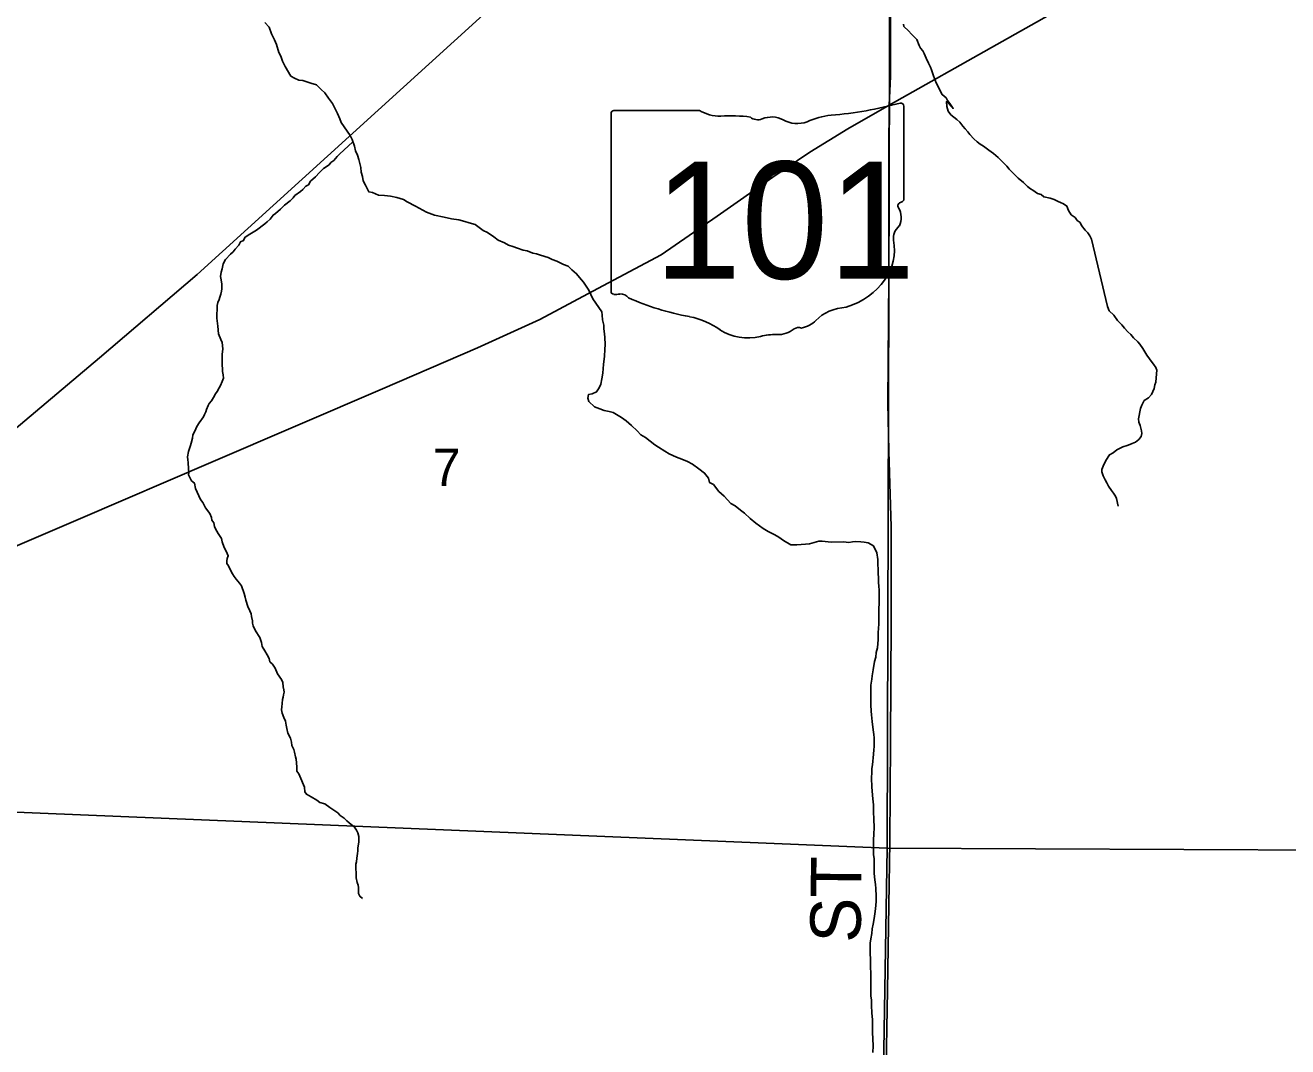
# Model space of a CAD drawing. Extents: x 0 to 34, y 0 to 22.
# Drawn here: x 3.229 to 4.651, y 17.976 to 19.126 of the extents above; entities that cross this region are included whole.
import ezdxf

# ---------------------------------------------------------------- set-up
doc = ezdxf.new("R2010")
doc.units = 0
for name, color, linetype in [('GM_X_County_Road', 7, 'Continuous'), ('GM_X_County_Road_Text', 7, 'Continuous'), ('GM_X_Minor_River', 7, 'Continuous'), ('GM_X_Rail_Line', 7, 'Continuous'), ('GM_X_Section', 7, 'Continuous'), ('GM_X_Section_Text', 7, 'Continuous'), ('GM_X_State_Location', 7, 'Continuous'), ('GM_X_State_Route', 7, 'Continuous'), ('GM_X_State_Shield', 7, 'Continuous')]:
    doc.layers.add(name, color=color, linetype=linetype)

msp = doc.modelspace()

# ---------------------------------------------------------------- linework, layer by layer
at = {"layer": 'GM_X_County_Road'}
for points in [[(4.202, 19.0361), (4.2034, 19.0684), (4.2035, 19.1565), (4.2038, 19.204), (4.2045, 19.2851), (4.2055, 19.3997), (4.207, 19.4991), (4.2084, 19.602), (4.2091, 19.7086), (4.2111, 19.8096), (4.2129, 19.9079), (4.2157, 20.0339), (4.2181, 20.1571), (4.2197, 20.2141), (4.2207, 20.2217)], [(4.1934, 17.3987), (4.1919, 17.4159), (4.1902, 17.4485), (4.1913, 17.53), (4.1927, 17.6289), (4.1943, 17.7254), (4.1962, 17.8328), (4.1982, 17.9321), (4.2, 18.0395), (4.2016, 18.1352), (4.2026, 18.2066), (4.2034, 18.3191), (4.2042, 18.4555), (4.2041, 18.5613), (4.2014, 18.6463), (4.2003, 18.7008), (4.2014, 18.8419), (4.2016, 18.9531), (4.2014, 18.9854), (4.202, 19.0361)]]:
    msp.add_lwpolyline(points, dxfattribs=at)
at = {"layer": 'GM_X_Minor_River'}
for points in [[(3.4987, 19.1289), (3.5037, 19.1236), (3.5064, 19.1164), (3.5098, 19.1096), (3.5118, 19.1043), (3.5145, 19.0952), (3.5168, 19.091), (3.5187, 19.0853), (3.5218, 19.0793), (3.5279, 19.0687), (3.5321, 19.0664), (3.537, 19.0642), (3.5416, 19.0638), (3.5507, 19.0608), (3.5568, 19.0589), (3.5621, 19.0536), (3.5663, 19.0499), (3.5705, 19.0438), (3.5751, 19.0378), (3.5778, 19.0325), (3.5805, 19.0264), (3.5832, 19.0207), (3.5847, 19.0165), (3.5947, 19.0018), (3.597, 18.9972), (3.5996, 18.9896), (3.6008, 18.9847), (3.6031, 18.9798), (3.6047, 18.9748), (3.607, 18.9657), (3.6074, 18.9604), (3.6089, 18.9555), (3.6097, 18.9509), (3.612, 18.946), (3.6158, 18.9384), (3.62, 18.9377), (3.6269, 18.9347), (3.6337, 18.9343), (3.6402, 18.9336), (3.6474, 18.9321), (3.655, 18.9299), (3.6592, 18.9272), (3.6683, 18.9224), (3.6809, 18.9156), (3.69, 18.9122), (3.7006, 18.91), (3.709, 18.9081), (3.7173, 18.907), (3.7242, 18.9048), (3.7288, 18.9036), (3.7356, 18.9014), (3.7447, 18.895), (3.7497, 18.8927), (3.7565, 18.8878), (3.7615, 18.8841), (3.7687, 18.881), (3.7733, 18.8784), (3.7779, 18.8769), (3.7832, 18.875), (3.7896, 18.8728), (3.7942, 18.8721), (3.8007, 18.8694), (3.8048, 18.8687), (3.8094, 18.8672), (3.8178, 18.8646), (3.8223, 18.8623), (3.8277, 18.8601), (3.8353, 18.8567), (3.8402, 18.8548), (3.8444, 18.8506), (3.8498, 18.8461), (3.8532, 18.8419), (3.8578, 18.8367), (3.8608, 18.8321), (3.8635, 18.8276), (3.8681, 18.8177)], [(4.2181, 19.127), (4.2185, 19.1244), (4.2238, 19.1195), (4.2269, 19.1157), (4.2299, 19.1127), (4.233, 19.11), (4.2357, 19.1032), (4.2372, 19.1002), (4.2399, 19.0971), (4.2414, 19.0941), (4.2437, 19.0888), (4.246, 19.0831), (4.2483, 19.0786), (4.2495, 19.0759), (4.2514, 19.0702), (4.2533, 19.0649), (4.2552, 19.0604), (4.2571, 19.057), (4.2598, 19.0513), (4.2614, 19.0479), (4.2659, 19.0441), (4.2675, 19.0411), (4.2701, 19.038), (4.274, 19.0323), (4.2663, 19.0399), (4.2667, 19.0346), (4.2683, 19.0293), (4.2713, 19.0251), (4.2782, 19.0198), (4.2813, 19.0168), (4.2847, 19.0123), (4.2874, 19.0092), (4.2904, 19.0058), (4.2927, 19.0028), (4.2973, 18.9979), (4.3011, 18.9945), (4.3042, 18.9922), (4.308, 18.9896), (4.3141, 18.9851), (4.3194, 18.9817), (4.3247, 18.9771), (4.3278, 18.9741), (4.3312, 18.9703), (4.3343, 18.9673), (4.3369, 18.9639), (4.3472, 18.9537)], [(3.583, 18.9806), (3.5978, 18.9948)], [(3.4501, 18.5479), (3.4463, 18.5536), (3.4433, 18.5589), (3.4422, 18.5616), (3.4415, 18.5658), (3.4392, 18.5685), (3.4389, 18.5715), (3.437, 18.5761), (3.4318, 18.5826), (3.4288, 18.5887), (3.4265, 18.5921), (3.4206, 18.6043), (3.4195, 18.6104), (3.4161, 18.6131), (3.4146, 18.6158), (3.4127, 18.6196), (3.4131, 18.6222), (3.4128, 18.6264), (3.4125, 18.6336), (3.4121, 18.6367), (3.4118, 18.6401), (3.413, 18.6461), (3.4149, 18.6526), (3.4157, 18.6552), (3.4173, 18.6609), (3.4177, 18.6647), (3.42, 18.6689), (3.4223, 18.6742), (3.425, 18.6783), (3.4296, 18.6851), (3.4308, 18.6877), (3.4323, 18.6908), (3.4331, 18.6934), (3.435, 18.6976), (3.4362, 18.7002), (3.4388, 18.7032), (3.4408, 18.7066), (3.4431, 18.7108), (3.445, 18.7134), (3.4473, 18.7176), (3.4488, 18.7202), (3.4508, 18.7248), (3.4523, 18.7286), (3.452, 18.7324), (3.4513, 18.7362), (3.4513, 18.7392), (3.4509, 18.743), (3.4506, 18.7517), (3.4507, 18.7551), (3.4515, 18.7616), (3.4508, 18.7688), (3.4493, 18.7722), (3.4467, 18.7783), (3.446, 18.7871), (3.4449, 18.7962), (3.4451, 18.8102), (3.4458, 18.8137), (3.4474, 18.8171), (3.4482, 18.8197), (3.4493, 18.8231), (3.4501, 18.8265), (3.4505, 18.8292), (3.4502, 18.8345), (3.4495, 18.8394), (3.4487, 18.8432), (3.4495, 18.8478), (3.4507, 18.8516), (3.4519, 18.8573), (3.4546, 18.8622), (3.4603, 18.8682), (3.463, 18.8708), (3.4653, 18.8738), (3.4695, 18.8784), (3.4715, 18.8821), (3.4749, 18.8836), (3.4764, 18.887), (3.4802, 18.8897), (3.4894, 18.8953), (3.4989, 18.9024), (3.5016, 18.9047), (3.5047, 18.9077), (3.5081, 18.9122), (3.5108, 18.9141), (3.5165, 18.919), (3.5211, 18.9235), (3.5272, 18.9283), (3.5306, 18.9317), (3.5326, 18.9344), (3.5391, 18.9389), (3.5417, 18.9411), (3.5448, 18.9449), (3.5478, 18.9464), (3.5501, 18.9502), (3.5559, 18.9551), (3.5605, 18.9603), (3.5647, 18.9645), (3.5712, 18.9686), (3.5731, 18.9712), (3.5765, 18.9738), (3.5803, 18.978), (3.583, 18.9806)], [(4.3472, 18.9537), (4.353, 18.9488), (4.3575, 18.9442), (4.361, 18.9416), (4.3636, 18.9401), (4.369, 18.9363), (4.3731, 18.9352), (4.3762, 18.9329), (4.383, 18.9314), (4.3876, 18.9296), (4.3922, 18.9273), (4.3948, 18.9262), (4.3982, 18.9247), (4.4021, 18.9224), (4.404, 18.9175), (4.407, 18.9126), (4.4112, 18.9095), (4.4135, 18.9061), (4.4169, 18.9039), (4.4185, 18.9005), (4.4227, 18.8952), (4.4257, 18.8921), (4.4277, 18.8887), (4.4296, 18.8849), (4.4478, 18.8091), (4.4497, 18.8045), (4.4547, 18.7996), (4.4589, 18.7935), (4.4638, 18.7886), (4.4669, 18.7848), (4.4707, 18.7807), (4.4741, 18.7777), (4.4772, 18.7739), (4.4818, 18.7693), (4.4841, 18.7667), (4.4875, 18.7618), (4.4921, 18.7546), (4.4952, 18.7504), (4.4971, 18.7478), (4.4994, 18.7444), (4.502, 18.7406), (4.5032, 18.7375), (4.5025, 18.7288), (4.5021, 18.7239), (4.501, 18.7212), (4.5003, 18.717), (4.4972, 18.7102), (4.4938, 18.7063), (4.4889, 18.7033), (4.4863, 18.698), (4.4848, 18.6945), (4.4826, 18.6827), (4.483, 18.679), (4.4845, 18.6752), (4.4861, 18.6691), (4.4865, 18.6664), (4.4857, 18.663), (4.4831, 18.6596), (4.4793, 18.6565), (4.4755, 18.655), (4.4729, 18.6538), (4.4698, 18.6527), (4.4649, 18.6511), (4.4581, 18.6477), (4.4543, 18.6446), (4.4501, 18.6423), (4.446, 18.6359), (4.443, 18.6294), (4.4415, 18.6256), (4.4415, 18.6229), (4.443, 18.6184), (4.4453, 18.6142), (4.4469, 18.6108), (4.4488, 18.607), (4.4522, 18.6021), (4.4545, 18.5991), (4.4568, 18.5956), (4.458, 18.593), (4.4599, 18.5846)], [(3.8681, 18.8177), (3.8784, 18.8033), (3.8788, 18.7995), (3.8792, 18.7942), (3.8804, 18.7881), (3.8804, 18.784), (3.8812, 18.7786), (3.8816, 18.7745), (3.882, 18.7665), (3.8817, 18.7608), (3.8813, 18.7532), (3.8802, 18.7441), (3.8799, 18.7395), (3.8795, 18.7342), (3.8784, 18.7277), (3.8773, 18.7217), (3.8754, 18.7178), (3.8724, 18.7133), (3.8675, 18.711), (3.8633, 18.7102), (3.8626, 18.706), (3.8638, 18.7022), (3.8702, 18.6962), (3.8759, 18.6939), (3.8809, 18.692), (3.8866, 18.6909), (3.8911, 18.6898), (3.895, 18.6876), (3.9003, 18.6842), (3.9056, 18.6804), (3.9117, 18.6751), (3.9182, 18.6691), (3.9224, 18.6649), (3.9273, 18.6619), (3.938, 18.6536), (3.9422, 18.6509), (3.9494, 18.6464), (3.954, 18.6434), (3.9624, 18.6396), (3.9685, 18.6374), (3.9749, 18.6348), (3.9803, 18.6317), (3.9875, 18.6265), (3.994, 18.6216), (3.9986, 18.6159), (3.9997, 18.6109), (4.0039, 18.6087), (4.01, 18.6011), (4.0161, 18.5958), (4.0237, 18.5875), (4.0283, 18.5849), (4.0344, 18.58), (4.039, 18.5766), (4.0455, 18.5705), (4.0516, 18.5652), (4.06, 18.5592), (4.0657, 18.5558), (4.0733, 18.552), (4.0778, 18.5494), (4.0828, 18.5456), (4.0912, 18.5407), (4.098, 18.5408), (4.1075, 18.5416), (4.112, 18.542), (4.1227, 18.5451), (4.1264, 18.5451), (4.1367, 18.544), (4.1504, 18.5441), (4.1564, 18.5437), (4.1606, 18.5441), (4.1644, 18.5445), (4.1701, 18.5441), (4.1739, 18.5438), (4.1781, 18.543), (4.1842, 18.5397), (4.188, 18.5317), (4.1892, 18.5245), (4.1892, 18.5188), (4.1896, 18.5135), (4.1897, 18.4987), (4.1901, 18.4941), (4.1905, 18.4903), (4.1906, 18.4744), (4.1902, 18.4694), (4.1903, 18.4523), (4.19, 18.4462), (4.1896, 18.4424), (4.1896, 18.4341), (4.1893, 18.4299), (4.1889, 18.425), (4.1874, 18.4196), (4.1867, 18.4143), (4.1852, 18.4094), (4.1837, 18.4003), (4.1826, 18.3934), (4.1823, 18.3896), (4.1812, 18.3828), (4.1813, 18.3607), (4.1817, 18.3535), (4.1821, 18.3494), (4.1829, 18.3418)], [(3.6086, 18.1425), (3.6056, 18.1452), (3.6044, 18.1483), (3.6041, 18.1525), (3.6041, 18.1551), (3.6038, 18.1578), (3.6026, 18.1608), (3.6016, 18.1658), (3.6016, 18.1722), (3.6013, 18.1753), (3.6013, 18.1813), (3.6021, 18.184), (3.6025, 18.1882), (3.6033, 18.1935), (3.6037, 18.1965), (3.6037, 18.1995), (3.6046, 18.2064), (3.6046, 18.2124), (3.6035, 18.2166), (3.602, 18.2197), (3.5998, 18.2231), (3.5937, 18.2277), (3.5911, 18.23), (3.5881, 18.2331), (3.5836, 18.2362), (3.5809, 18.2392), (3.5719, 18.245), (3.5662, 18.2492), (3.5609, 18.2508), (3.5575, 18.2535), (3.5508, 18.2573), (3.5458, 18.26), (3.544, 18.2627), (3.5436, 18.268), (3.5425, 18.2707), (3.5395, 18.2779), (3.5369, 18.2829), (3.5347, 18.2859), (3.5347, 18.2905), (3.5344, 18.2954), (3.534, 18.2996), (3.5333, 18.3023), (3.5322, 18.3076), (3.5315, 18.3106), (3.5292, 18.3148), (3.5289, 18.3186), (3.5278, 18.3232), (3.5248, 18.3289), (3.5237, 18.3342), (3.523, 18.338), (3.5219, 18.3422), (3.52, 18.3464), (3.5182, 18.3514), (3.5174, 18.3552), (3.5179, 18.3586), (3.5183, 18.3624), (3.5187, 18.3666), (3.5195, 18.3692), (3.5199, 18.3719), (3.5206, 18.3749), (3.5203, 18.3776), (3.5196, 18.381), (3.5192, 18.3859), (3.5174, 18.3893), (3.5132, 18.3958), (3.5103, 18.4019), (3.5073, 18.4065), (3.5046, 18.4092), (3.5035, 18.413), (3.5013, 18.4172), (3.4987, 18.4214), (3.4957, 18.4264), (3.495, 18.4309), (3.4931, 18.4366), (3.4882, 18.4439), (3.4856, 18.4496), (3.4849, 18.4527), (3.4849, 18.4553), (3.4838, 18.4603), (3.4835, 18.4633), (3.482, 18.4667), (3.4797, 18.4713), (3.4775, 18.4785), (3.4768, 18.482), (3.4757, 18.4861), (3.4724, 18.4949), (3.4701, 18.4976), (3.4664, 18.5022), (3.4641, 18.5052), (3.4622, 18.5083), (3.46, 18.5125), (3.4578, 18.5171), (3.4559, 18.5197), (3.4559, 18.5228), (3.4563, 18.5254), (3.4575, 18.5284), (3.4564, 18.5311), (3.4545, 18.5353), (3.453, 18.538), (3.4508, 18.5441), (3.4501, 18.5479)], [(4.1829, 18.3418), (4.1837, 18.3326), (4.1845, 18.3273), (4.1849, 18.3235), (4.1849, 18.3137), (4.1846, 18.3099), (4.1842, 18.3053), (4.1831, 18.2931), (4.1824, 18.289), (4.1824, 18.2848), (4.1821, 18.2783), (4.1825, 18.2685), (4.1829, 18.2635), (4.1833, 18.2548), (4.1841, 18.2483), (4.1841, 18.2415), (4.1846, 18.2309), (4.185, 18.2236), (4.1847, 18.2138), (4.1843, 18.21), (4.1843, 18.2009), (4.1844, 18.1917), (4.1848, 18.1876), (4.1849, 18.1708), (4.1857, 18.1636), (4.1864, 18.1583), (4.1868, 18.1541), (4.1873, 18.1454), (4.1873, 18.1397), (4.1869, 18.1348), (4.1862, 18.1279), (4.1851, 18.12), (4.184, 18.1139), (4.1829, 18.1085), (4.1822, 18.1032), (4.1811, 18.0971), (4.1803, 18.0922), (4.1804, 18.0812), (4.1808, 18.074), (4.1808, 18.066), (4.1812, 18.058), (4.1814, 18.0326), (4.1818, 18.0284), (4.1818, 18.0223), (4.1822, 18.014), (4.183, 18.006), (4.1831, 17.9919), (4.1835, 17.9847), (4.1839, 17.9768), (4.1836, 17.9692)]]:
    msp.add_lwpolyline(points, dxfattribs=at)
at = {"layer": 'GM_X_Rail_Line'}
msp.add_lwpolyline([(2.3438, 17.8832), (2.4082, 17.9379), (2.5423, 18.061), (2.7943, 18.2844), (3.1322, 18.5996), (3.3125, 18.7514), (3.4225, 18.8451), (3.8301, 19.2157), (4.2487, 19.5941), (4.47, 19.794), (4.5566, 19.8598), (4.6465, 19.9302), (4.7011, 19.9679), (5.2057, 20.3431), (5.7213, 20.7403), (5.9437, 20.9)], dxfattribs=at)
at = {"layer": 'GM_X_Section'}
for points in [[(3.2151, 19.2391), (4.2026, 19.2018), (4.1997, 18.1993), (3.2, 18.2405)], [(4.2026, 19.2018), (5.2108, 19.1947), (5.2018, 18.1949), (4.1997, 18.1993)], [(4.1997, 18.1993), (4.1831, 17.1984), (3.1868, 17.2222), (3.2, 18.2405)], [(4.1997, 18.1993), (5.2018, 18.1949), (5.1818, 17.1932), (4.1831, 17.1984)]]:
    msp.add_lwpolyline(points, close=True, dxfattribs=at)
at = {"layer": 'GM_X_State_Route'}
msp.add_lwpolyline([(3.2071, 18.5344), (3.2912, 18.5707), (3.438, 18.6337), (3.6313, 18.7164), (3.7384, 18.7627), (3.8083, 18.7947), (3.868, 18.8264), (3.9451, 18.8676), (4.0083, 18.9108), (4.0708, 18.9549), (4.1126, 18.9832), (4.1555, 19.0093), (4.202, 19.0361), (4.323, 19.1042), (4.4211, 19.1597), (4.4727, 19.1914), (4.604, 19.2798), (4.6509, 19.3078)], dxfattribs=at)
at = {"layer": 'GM_X_State_Shield'}
for p, q in [((3.8887, 19.0265), (3.8887, 18.8264)), ((3.9885, 19.03), (3.8919, 19.03)), ((4.2183, 18.9302), (4.2183, 19.0349)), ((4.2182, 18.9303), (4.2183, 18.9302))]:
    msp.add_line(p, q, dxfattribs=at)
for centre, major_axis, start_param, end_param in [((4.1009, 19.3028), (0.3495, 0), 4.814394, 5.042369), ((4.2146, 19.0354), (0.00367, 0), 6.141152, 7.989035), ((3.8925, 19.027), (0.00382, 0), 1.712693, 3.28349), ((4.0114, 19.0532), (0.037, 0), 4.042523, 4.731795), ((4.0237, 18.9176), (0.133, 0), 1.404758, 1.657858), ((4.0696, 19.0049), (0.0222, 0), 0.950623, 2.079405), ((4.1455, 18.9689), (0.0703, 0), 1.699011, 2.107814), ((4.0539, 19.028), (0.0107, 0), 3.836095, 5.185415), ((4.0983, 19.0366), (0.0267, 0), 4.081561, 5.145723), ((4.2174, 18.9226), (0.00568, 0), 1.883978, 3.671073), ((4.2144, 18.9298), (0.00393, 0), 5.05454, 6.418171), ((4.1813, 18.9093), (0.0341, 0), 5.934695, 6.695948), ((4.2314, 18.8864), (0.0248, 0), 2.387724, 3.262537), ((4.1204, 18.8731), (0.0874, 0), 5.101752, 6.440018), ((3.8925, 18.826), (0.00385, 0), 3.00124, 4.508301), ((3.8931, 18.8464), (0.0294, 0), 4.665946, 4.897461), ((3.8991, 18.8149), (0.0106, 0), 0.519207, 1.627899), ((4.0329, 18.9947), (0.2524, 0), 4.195997, 4.488961), ((3.9577, 18.7365), (0.079, 0), 0.823519, 1.323587), ((4.1573, 18.7702), (0.0479, 0), 1.647645, 2.488434), ((4.0431, 18.8139), (0.0501, 0), 4.026481, 4.996735), ((4.0757, 18.7989), (0.0267, 0), 4.691044, 5.507374), ((4.0999, 18.7795), (0.00752, 0), 1.147584, 2.315152), ((4.0966, 18.807), (0.0282, 0), 4.937069, 5.64225), ((4.072, 18.7447), (0.0412, 0), 1.495662, 1.94098)]:
    msp.add_ellipse(centre, major_axis=major_axis, ratio=0.8, start_param=start_param, end_param=end_param, dxfattribs=at)

# ---------------------------------------------------------------- texts
at = {"layer": 'GM_X_County_Road_Text'}
msp.add_text('ST', height=0.05682, rotation=89.4097, dxfattribs=at).set_placement((4.1697, 18.0927))
at = {"layer": 'GM_X_Section_Text'}
msp.add_text('7', height=0.0419, rotation=0, dxfattribs=at).set_placement((3.6879, 18.6072))
at = {"layer": 'GM_X_State_Location'}
for s in ['s', 'r']:
    msp.add_text(s, height=0.000189, dxfattribs=at).set_placement((4.0498, 18.9132))
msp.add_text('101', height=0.000189, rotation=0, dxfattribs=at).set_placement((3.9829, 18.8994))
at = {"layer": 'GM_X_State_Shield'}
msp.add_text('101', height=0.13184, dxfattribs=at).set_placement((3.9373, 18.8405))

doc.saveas('drawing.dxf')
